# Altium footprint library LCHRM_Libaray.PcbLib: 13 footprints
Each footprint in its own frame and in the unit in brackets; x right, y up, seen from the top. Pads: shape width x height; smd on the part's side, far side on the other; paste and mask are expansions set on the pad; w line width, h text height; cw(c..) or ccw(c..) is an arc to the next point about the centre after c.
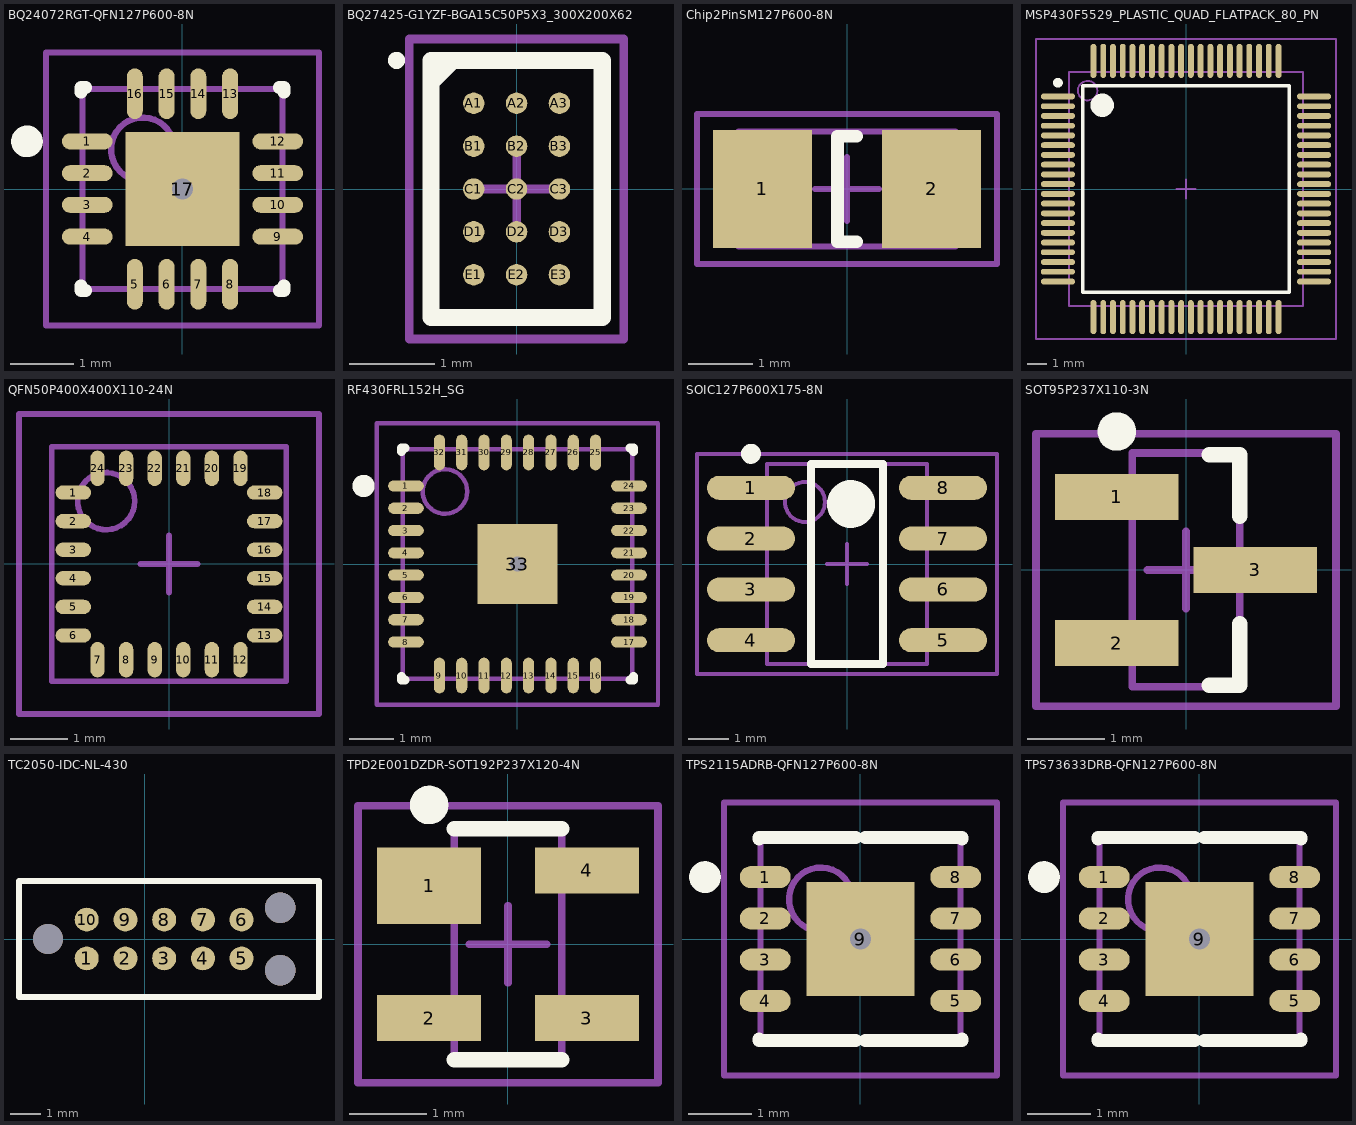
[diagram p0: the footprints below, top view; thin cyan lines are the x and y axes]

## BQ24072RGT-QFN127P600-8N [mm]
height 1
pads (17):
  oval 0.8x0.25 smd: 1(-1.5,0.75) 2(-1.5,0.25) 3(-1.5,-0.25) 4(-1.5,-0.75) 9(1.5,-0.75) 10(1.5,-0.25) 11(1.5,0.25) 12(1.5,0.75)
  oval 0.25x0.8 smd: 5(-0.75,-1.5) 6(-0.25,-1.5) 7(0.25,-1.5) 8(0.75,-1.5) 13(0.75,1.5) 14(0.25,1.5) 15(-0.25,1.5) 16(-0.75,1.5)
  rect 1.8x1.8 smd: 17(0,0)
via 0,0 diameter 0.66 hole 0.33
Top Overlay:
  circle w0.25: c-2.45,0.75 r0.125
  lines w0.2: -1.6,-1.525 -1.6,-1.6 -1.525,-1.6 ; -1.6,1.525 -1.6,1.6 -1.525,1.6 ; 1.525,-1.6 1.6,-1.6 1.6,-1.525 ; 1.525,1.6 1.6,1.6 1.6,1.525
M13 Component Bodies Top:
  circle w0.1: c-0.625,0.625 r0.5
  lines w0.1: -1.575,-1.575 -1.575,1.575 1.575,1.575 1.575,-1.575 -1.575,-1.575
M15  Courtyards Top:
  lines w0.1: -0.5,0 0.5,0 ; 0,-0.5 0,0.5 ; -2.15,-2.15 -2.15,2.15 2.15,2.15 2.15,-2.15 -2.15,-2.15
3D body: height 1, standoff 0.08, extent -1.575,-1.575 1.575,1.575

## BQ27425-G1YZF-BGA15C50P5X3_300X200X62 [mm] "BGA, 15-Leads, Body 3.0x2.0mm,  Pitch 0.50mm"
height 0.625
pads (15):
  round 0.25 smd: A1(-0.5,1) A2(0,1) A3(0.5,1) B1(-0.5,0.5) B2(0,0.5) B3(0.5,0.5) C1(-0.5,0) C2(0,0) C3(0.5,0) D1(-0.5,-0.5) D2(0,-0.5) D3(0.5,-0.5) E1(-0.5,-1) E2(0,-1) E3(0.5,-1)
Top Overlay:
  circle w0.1: c-1.4,1.5 r0.05
  region: -0.742,1.5 -1,1.242 -1,1.5
  lines w0.2: -1,1.242 -0.742,1.5 ; -1,-1.5 -1,1.5 1,1.5 1,-1.5 -1,-1.5
M13 Component Bodies Top:
  lines w0.1: -1,-1.5 -1,1.5 1,1.5 1,-1.5 -1,-1.5
M15  Courtyards Top:
  lines w0.1: -0.5,0 0.5,0 ; 0,-0.5 0,0.5 ; -1.25,-1.75 -1.25,1.75 1.25,1.75 1.25,-1.75 -1.25,-1.75
3D body: height 0.63, standoff 0.15, extent -1,-1.5 1,1.5

## Chip2PinSM127P600-8N [mm]
height 1.8
pads (2):
  rect 1.55x1.85 smd: 1(-1.325,0) 2(1.325,0)
Top Overlay:
  lines w0.2: 0.15,-0.825 -0.15,-0.825 -0.15,0.825 0.15,0.825
M13 Component Bodies Top:
  lines w0.1: -1.7,-0.9 1.7,-0.9 1.7,0.9 -1.7,0.9 -1.7,-0.9
M15  Courtyards Top:
  lines w0.1: -0.5,0 0.5,0 ; 0,-0.5 0,0.5 ; -2.35,-1.175 2.35,-1.175 2.35,1.175 -2.35,1.175 -2.35,-1.175
3D body: height 1.8, standoff 0, extent -1.7,-0.9 1.7,0.9

## MSP430F5529_PLASTIC_QUAD_FLATPACK_80_PN [mm] "TSQFP, 80-Leads, Body 14.2x14.2mm (max), Pitch 0.50mm, IPC Medium Density"
height 1.6
pads (80):
  oval 1.75x0.3 smd: 1(-6.575,4.75) 2(-6.575,4.25) 3(-6.575,3.75) 4(-6.575,3.25) 5(-6.575,2.75) 6(-6.575,2.25) 7(-6.575,1.75) 8(-6.575,1.25) 9(-6.575,0.75) 10(-6.575,0.25) 11(-6.575,-0.25) 12(-6.575,-0.75) 13(-6.575,-1.25) 14(-6.575,-1.75) 15(-6.575,-2.25) 16(-6.575,-2.75) 17(-6.575,-3.25) 18(-6.575,-3.75) 19(-6.575,-4.25) 20(-6.575,-4.75) 41(6.575,-4.75) 42(6.575,-4.25) 43(6.575,-3.75) 44(6.575,-3.25) 45(6.575,-2.75) 46(6.575,-2.25) 47(6.575,-1.75) 48(6.575,-1.25) 49(6.575,-0.75) 50(6.575,-0.25) 51(6.575,0.25) 52(6.575,0.75) 53(6.575,1.25) 54(6.575,1.75) 55(6.575,2.25) 56(6.575,2.75) 57(6.575,3.25) 58(6.575,3.75) 59(6.575,4.25) 60(6.575,4.75)
  oval 0.3x1.75 smd: 21(-4.75,-6.575) 22(-4.25,-6.575) 23(-3.75,-6.575) 24(-3.25,-6.575) 25(-2.75,-6.575) 26(-2.25,-6.575) 27(-1.75,-6.575) 28(-1.25,-6.575) 29(-0.75,-6.575) 30(-0.25,-6.575) 31(0.25,-6.575) 32(0.75,-6.575) 33(1.25,-6.575) 34(1.75,-6.575) 35(2.25,-6.575) 36(2.75,-6.575) 37(3.25,-6.575) 38(3.75,-6.575) 39(4.25,-6.575) 40(4.75,-6.575) 61(4.75,6.575) 62(4.25,6.575) 63(3.75,6.575) 64(3.25,6.575) 65(2.75,6.575) 66(2.25,6.575) 67(1.75,6.575) 68(1.25,6.575) 69(0.75,6.575) 70(0.25,6.575) 71(-0.25,6.575) 72(-0.75,6.575) 73(-1.25,6.575) 74(-1.75,6.575) 75(-2.25,6.575) 76(-2.75,6.575) 77(-3.25,6.575) 78(-3.75,6.575) 79(-4.25,6.575) 80(-4.75,6.575)
Top Overlay:
  circle w0.6: c-4.3,4.3 r0.3
  circle w0.25: c-6.575,5.45 r0.125
  lines w0.2: -5.3,-5.3 5.3,-5.3 5.3,5.3 -5.3,5.3 -5.3,-5.3
M13 Component Bodies Top:
  circle w0.1: c-5.05,5.05 r0.5
  lines w0.1: -6,-6 6,-6 6,6 -6,6 -6,-6
M15  Courtyards Top:
  lines w0.1: -0.5,0 0.5,0 ; 0,-0.5 0,0.5 ; -7.7,-7.7 7.7,-7.7 7.7,7.7 -7.7,7.7 -7.7,-7.7
3D body: height 1.6, standoff 0.08, extent -6,-6 6,6

## PCBComponent_1 [mm]
3D body: height 0, standoff -5.6, extent -16.117,-8.14 16.083,7.86

## QFN50P400X400X110-24N [mm] "Double Row QFN, 24-Leads, Body 4.1x4.1mm (max), Pitch 0.50mm, IPC Medium Density"
height 1.1
pads (24):
  oval 0.62x0.25 smd: 1(-1.675,1.25) 2(-1.675,0.75) 3(-1.675,0.25) 4(-1.675,-0.25) 5(-1.675,-0.75) 6(-1.675,-1.25) 13(1.675,-1.25) 14(1.675,-0.75) 15(1.675,-0.25) 16(1.675,0.25) 17(1.675,0.75) 18(1.675,1.25)
  oval 0.25x0.62 smd: 7(-1.25,-1.675) 8(-0.75,-1.675) 10(0.25,-1.675) 11(0.75,-1.675) 12(1.25,-1.675) 19(1.25,1.675) 20(0.75,1.675) 21(0.25,1.675) 22(-0.25,1.675) 23(-0.75,1.675) 24(-1.25,1.675)
  oval 0.25x0.62 smd mask+0.102: 9(-0.25,-1.675)
M13 Component Bodies Top:
  circle w0.1: c-1.1,1.1 r0.5
  lines w0.1: -2.05,-2.05 2.05,-2.05 2.05,2.05 -2.05,2.05 -2.05,-2.05
M15  Courtyards Top:
  lines w0.1: -0.5,0 0.5,0 ; 0,-0.5 0,0.5 ; -2.625,-2.625 2.625,-2.625 2.625,2.625 -2.625,2.625 -2.625,-2.625
3D body: height 1.1, standoff 0.11, extent -2.05,-2.05 2.05,2.05

## RF430FRL152H_SG [mm]
height 1
pads (33):
  oval 0.8x0.25 smd: 1(-2.5,1.75) 2(-2.5,1.25) 3(-2.5,0.75) 4(-2.5,0.25) 5(-2.5,-0.25) 6(-2.5,-0.75) 7(-2.5,-1.25) 8(-2.5,-1.75) 17(2.5,-1.75) 18(2.5,-1.25) 19(2.5,-0.75) 20(2.5,-0.25) 21(2.5,0.25) 22(2.5,0.75) 23(2.5,1.25) 24(2.5,1.75)
  oval 0.25x0.8 smd: 9(-1.75,-2.5) 10(-1.25,-2.5) 11(-0.75,-2.5) 12(-0.25,-2.5) 13(0.25,-2.5) 14(0.75,-2.5) 15(1.25,-2.5) 16(1.75,-2.5) 25(1.75,2.5) 26(1.25,2.5) 27(0.75,2.5) 28(0.25,2.5) 29(-0.25,2.5) 30(-0.75,2.5) 31(-1.25,2.5) 32(-1.75,2.5)
  rect 1.8x1.8 smd: 33(0,0)
via 0,0 diameter 0.66 hole 0.33
Top Overlay:
  circle w0.25: c-3.45,1.75 r0.125
  lines w0.2: -2.6,-2.525 -2.6,-2.6 -2.525,-2.6 ; -2.6,2.525 -2.6,2.6 -2.525,2.6 ; 2.525,-2.6 2.6,-2.6 2.6,-2.525 ; 2.525,2.6 2.6,2.6 2.6,2.525
M13 Component Bodies Top:
  circle w0.1: c-1.625,1.625 r0.5
  lines w0.1: -2.575,-2.575 2.575,-2.575 2.575,2.575 -2.575,2.575 -2.575,-2.575
M15  Courtyards Top:
  lines w0.1: -0.5,0 0.5,0 ; 0,-0.5 0,0.5 ; -3.15,-3.15 3.15,-3.15 3.15,3.15 -3.15,3.15 -3.15,-3.15
3D body: height 1, standoff 0.08, extent -2.575,-2.575 2.575,2.575

## SOIC127P600X175-8N [mm] "SOIC, 8-Leads, Body 5.0x4.0mm (max), Pitch 1.27mm, IPC Medium Density"
height 1.75
pads (8):
  oval 2.2x0.6 smd: 1(-2.4,1.905) 2(-2.4,0.635) 3(-2.4,-0.635) 4(-2.4,-1.905) 5(2.4,-1.905) 6(2.4,-0.635) 7(2.4,0.635) 8(2.4,1.905)
Top Overlay:
  circle w0.25: c-2.4,2.755 r0.125
  circle w0.6: c0.1,1.5 r0.3
  lines w0.2: -0.9,-2.5 -0.9,2.5 0.9,2.5 0.9,-2.5 -0.9,-2.5
M13 Component Bodies Top:
  circle w0.1: c-1.05,1.55 r0.5
  lines w0.1: -2,-2.5 -2,2.5 2,2.5 2,-2.5 -2,-2.5
M15  Courtyards Top:
  lines w0.1: -0.5,0 0.5,0 ; 0,-0.5 0,0.5 ; -3.75,-2.75 -3.75,2.75 3.75,2.75 3.75,-2.75 -3.75,-2.75
3D body: height 1.75, standoff 0.1, extent -2,-2.5 2,2.5

## SOT95P237X110-3N [mm] "SOT23, 3-Leads, Body 3.0x2.6mm (max), Pitch 0.95mm, IPC Medium Density"
height 1.1
pads (3):
  rect 1.6x0.6 smd: 1(-0.9,0.95) 2(-0.9,-0.95) 3(0.9,0)
Top Overlay:
  circle w0.25: c-0.9,1.8 r0.125
  lines w0.2: 0.3,-1.5 0.7,-1.5 0.7,-0.7 ; 0.3,1.5 0.7,1.5 0.7,0.7
M13 Component Bodies Top:
  lines w0.1: -0.7,-1.52 0.7,-1.52 0.7,1.52 -0.7,1.52 -0.7,-1.52
M15  Courtyards Top:
  lines w0.1: -0.5,0 0.5,0 ; 0,-0.5 0,0.5 ; -1.95,-1.77 1.95,-1.77 1.95,1.77 -1.95,1.77 -1.95,-1.77
3D body: height 1.1, standoff 0.05, extent -0.7,-1.52 0.7,1.52

## TC2050-IDC-NL-430 [mm]
pads (10):
  round 0.787 smd: 1(-1.905,-0.635) 2(-0.635,-0.635) 3(0.635,-0.635) 4(1.905,-0.635) 5(3.175,-0.635) 6(3.175,0.635) 7(1.905,0.635) 8(0.635,0.635) 9(-0.635,0.635) 10(-1.905,0.635)
via -3.175,0 diameter 0.991 hole 0.991
via 4.445,1.028 diameter 0.991 hole 0.991
via 4.445,-1.028 diameter 0.991 hole 0.991
Top Overlay:
  lines w0.2: -4.127,-1.905 5.715,-1.905 5.715,1.905 -4.127,1.905 -4.127,-1.905

## TPD2E001DZDR-SOT192P237X120-4N [mm] "SOT143, 4-Leads, Body 3.0x2.6mm (max), Pitch 1.92mm, IPC Medium Density"
height 1.2
pads (4):
  rect 1.35x1 smd: 1(-1.025,0.76)
  rect 1.35x0.6 smd: 2(-1.025,-0.96) 3(1.025,-0.96) 4(1.025,0.96)
Top Overlay:
  circle w0.25: c-1.025,1.81 r0.125
  lines w0.2: -0.7,-1.5 0.7,-1.5 ; -0.7,1.5 0.7,1.5
M13 Component Bodies Top:
  lines w0.1: -0.7,-1.52 -0.7,1.52 0.7,1.52 0.7,-1.52 -0.7,-1.52
M15  Courtyards Top:
  lines w0.1: -0.5,0 0.5,0 ; 0,-0.5 0,0.5 ; -1.95,-1.8 -1.95,1.8 1.95,1.8 1.95,-1.8 -1.95,-1.8
3D body: height 1.2, standoff 0.15, extent -0.7,-1.52 0.7,1.52

## TPS2115ADRB-QFN127P600-8N [mm]
height 1
pads (9):
  oval 0.8x0.35 smd: 1(-1.5,0.975) 2(-1.5,0.325) 3(-1.5,-0.325) 4(-1.5,-0.975) 5(1.5,-0.975) 6(1.5,-0.325) 7(1.5,0.325) 8(1.5,0.975)
  rect 1.7x1.8 smd: 9(0,0)
via 0,0 diameter 0.66 hole 0.33
Top Overlay:
  circle w0.25: c-2.45,0.975 r0.125
  lines w0.2: -1.6,-1.575 -1.6,-1.6 -0.075,-1.6 ; -1.6,1.575 -1.6,1.6 -0.075,1.6 ; 0.075,-1.6 1.6,-1.6 1.6,-1.575 ; 0.075,1.6 1.6,1.6 1.6,1.575
M13 Component Bodies Top:
  circle w0.1: c-0.625,0.625 r0.5
  lines w0.1: -1.575,-1.575 -1.575,1.575 1.575,1.575 1.575,-1.575 -1.575,-1.575
M15  Courtyards Top:
  lines w0.1: -0.5,0 0.5,0 ; 0,-0.5 0,0.5 ; -2.15,-2.15 -2.15,2.15 2.15,2.15 2.15,-2.15 -2.15,-2.15
3D body: height 1, standoff 0.08, extent -1.575,-1.575 1.575,1.575

## TPS73633DRB-QFN127P600-8N [mm]
height 1
pads (9):
  oval 0.8x0.35 smd: 1(-1.5,0.975) 2(-1.5,0.325) 3(-1.5,-0.325) 4(-1.5,-0.975) 5(1.5,-0.975) 6(1.5,-0.325) 7(1.5,0.325) 8(1.5,0.975)
  rect 1.7x1.8 smd: 9(0,0)
via 0,0 diameter 0.66 hole 0.33
Top Overlay:
  circle w0.25: c-2.45,0.975 r0.125
  lines w0.2: -1.6,-1.575 -1.6,-1.6 -0.075,-1.6 ; -1.6,1.575 -1.6,1.6 -0.075,1.6 ; 0.075,-1.6 1.6,-1.6 1.6,-1.575 ; 0.075,1.6 1.6,1.6 1.6,1.575
M13 Component Bodies Top:
  circle w0.1: c-0.625,0.625 r0.5
  lines w0.1: -1.575,-1.575 -1.575,1.575 1.575,1.575 1.575,-1.575 -1.575,-1.575
M15  Courtyards Top:
  lines w0.1: -0.5,0 0.5,0 ; 0,-0.5 0,0.5 ; -2.15,-2.15 -2.15,2.15 2.15,2.15 2.15,-2.15 -2.15,-2.15
3D body: height 1, standoff 0.08, extent -1.575,-1.575 1.575,1.575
